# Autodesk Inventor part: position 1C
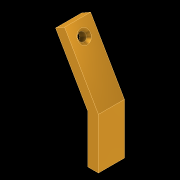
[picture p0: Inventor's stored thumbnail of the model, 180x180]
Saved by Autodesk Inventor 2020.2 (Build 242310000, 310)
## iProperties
Category: 1
Manager: PART
Company: 27
Created: 2020-10
Part Number: position 1C
Material: Generic
Document SubType Name: Modeling
Designer: Apardo
Density: 1 g/cm^3
Appearance: Metal 1800F Hot
Vendor: 1C
Project: PLATE ROLLING MACHINE
Cost Center: 1
Engineer: STEEL C45
Stock Number: 3.3
Engr Approved By: D. JAEGER
Author: Apardo
Revision Number: 1.0
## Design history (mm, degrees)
sketch "Sketch1"
  geometry: L1 (-4, -35)-(-4, 1.856); L2 (-4, 1.856)-(-28.928, 45.033); L3 (-28.928, 45.033)-(-22, 49.033); L4 (-22, 49.033)-(4, 4); L5 (4, 4)-(4, -35); L6 (4, -35)-(-4, -35); 1 further point
  constraints: 12 end point, 3 perpendicular, 1 equal length, 1 parallel, 1 vertical
  dimensions: "d0" = 8 distance of L2.end L3.end; "d1" = 4 distance from line of point (0, 0) L5 (= 0.5 x d0); "d2" = 39 distance of L4.end L5.end; "d3" = 150 deg angle of L1 L2; "d4" = 52 distance of L3.end L4.end; "d6" = 35 distance from line of L6 point (0, 0)
extrude "Extrusion1" new body sketch "Sketch1" stored distance "d7" = 20; taper "d8" = 0 deg
sketch "Sketch2"
  geometry: L1 (20, 0)-(0, 0) reference; 2 further points
  constraints: 1 vertical alignment
  dimensions: "d9" = 10 distance from line of point (10, -10) L1
hole "Hole1" sketch "Sketch2" at (10, -10) diameter "d10" = 6.2; stored, may be unused: countersink angle "d14" = 90 deg, drill point angle "d16" = 118 deg; dims "d11" = 12, "d12" = 10, "d13" = 2, "d15" = 8
body "Solid1"
